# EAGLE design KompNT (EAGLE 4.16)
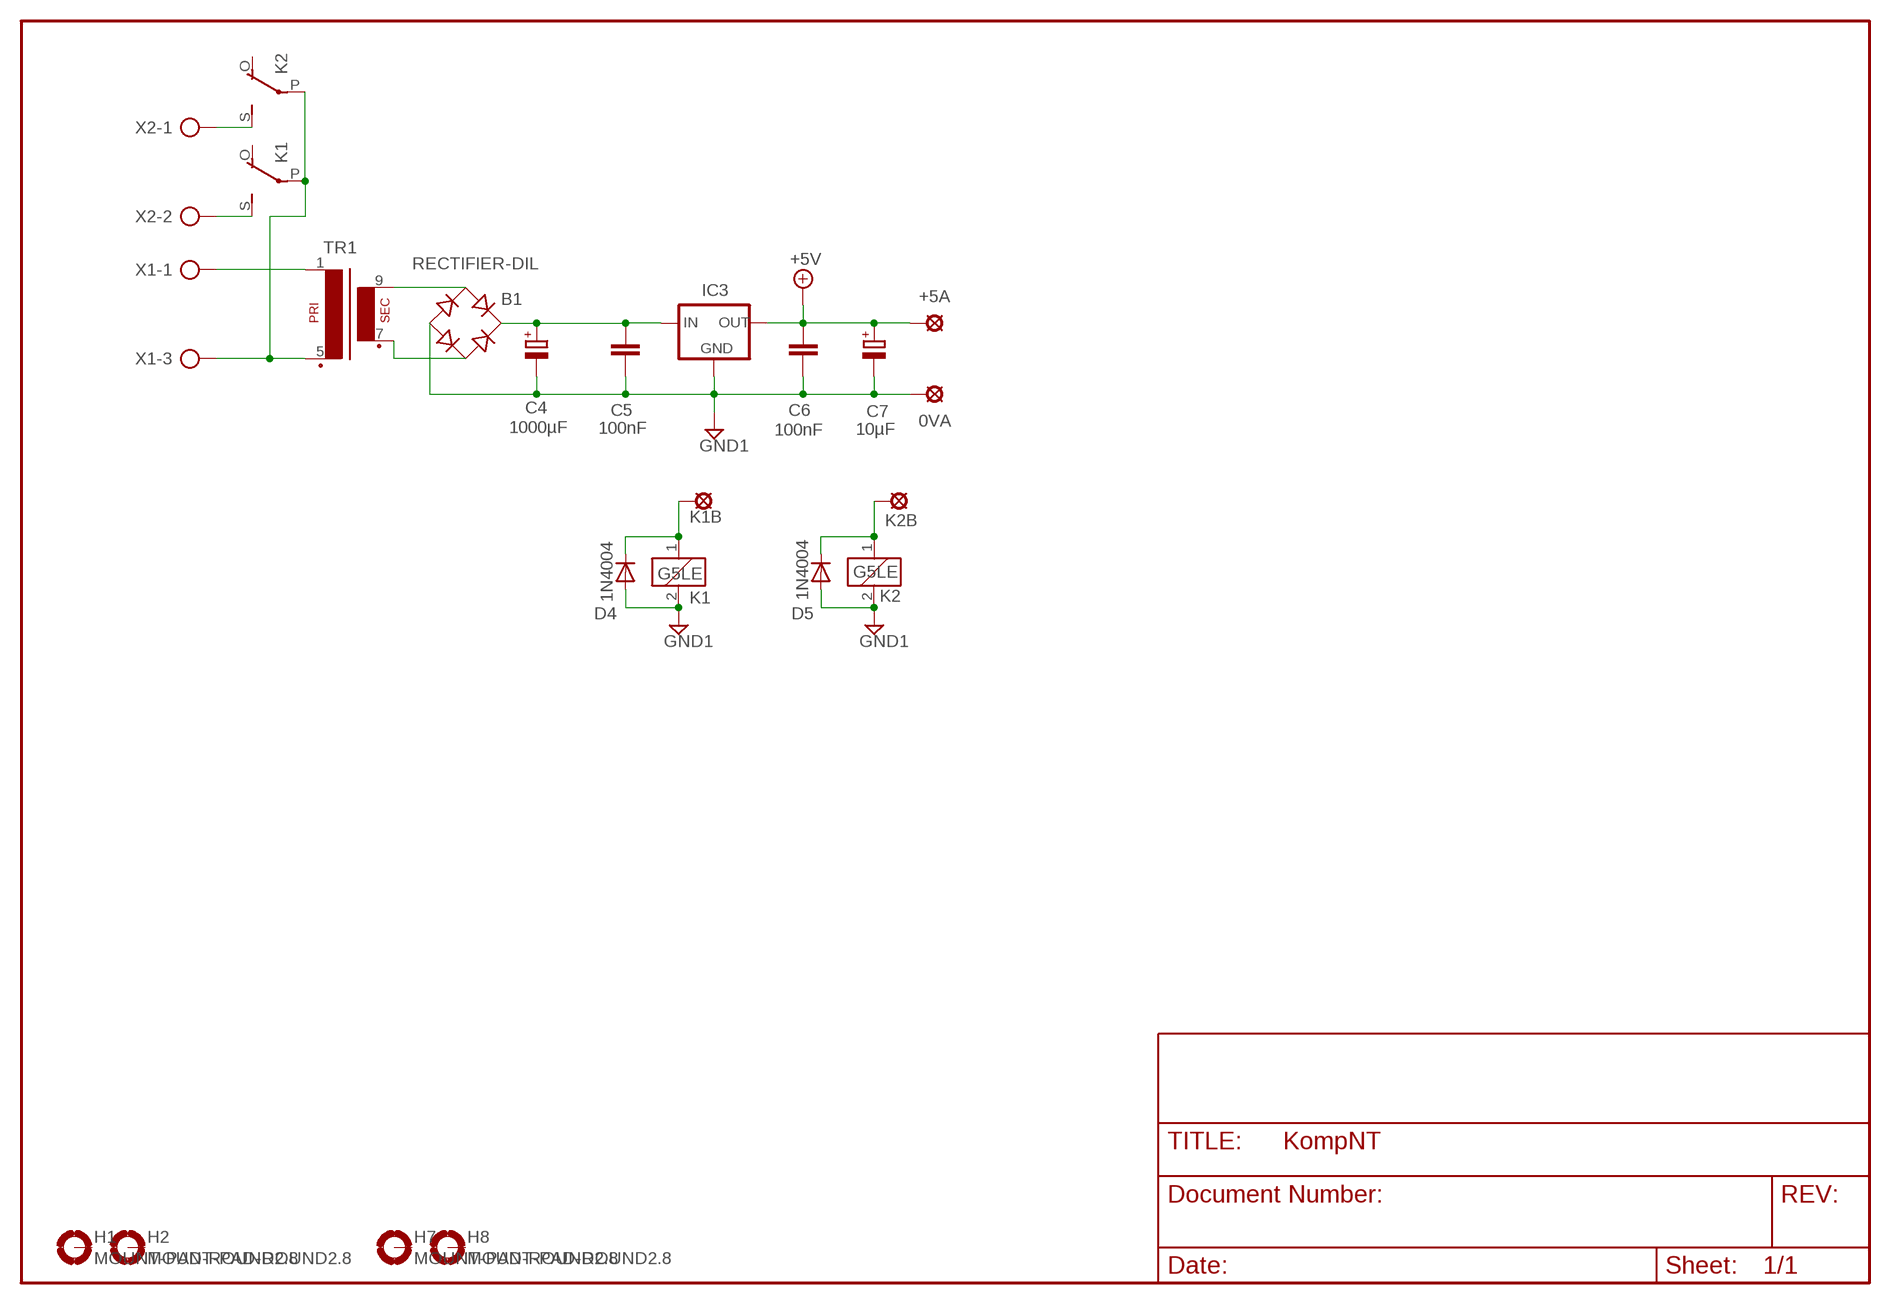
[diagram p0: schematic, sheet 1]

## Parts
0VA  LSP10  [LSP10]
+5A  LSP10  [LSP10]
B1  RECTIFIER-DIL  [B-DIL]
C4  1000µF  CPOL-EUE5-13  [E5-13]
C5  100nF  C-EU025-025X050  [C025-025X050]
C6  100nF  C-EU025-025X050  [C025-025X050]
C7  10µF  CPOL-EUE2.5-5  [E2,5-5]
D4  1N4004  [DO41-10]
D5  1N4004  [DO41-10]
H1  MOUNT-PAD-ROUND2.8  [2,8-PAD]
H2  MOUNT-PAD-ROUND2.8  [2,8-PAD]
H7  MOUNT-PAD-ROUND2.8  [2,8-PAD]
H8  MOUNT-PAD-ROUND2.8  [2,8-PAD]
IC3  78XXS  [78XXS]
K1  G5LE  [G5LE]
K1B  LSP10  [LSP10]
K2  G5LE  [G5LE]
K2B  LSP10  [LSP10]
TR1  EI42-1  [EI42-1]
X1  AK500/3  [AK500/3]
X2  AK500/2  [AK500/2]

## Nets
+5V: +5A.MP C6.2 C7.+ IC3.OUT
GND1: 0VA.MP B1.- C4.- C5.1 C6.1 C7.- D4.A D5.A IC3.GND K1.2 K2.2
N$34: B1.AC1 TR1.9(S4)
N$35: B1.AC2 TR1.7(S3)
N$36: TR1.1 X1.1
N$37: B1.+ C4.+ C5.2 IC3.IN
N$38: D4.C K1.1 K1B.MP
N$39: K1.P(2:P) K2.P(2:P) TR1.5(P2) X1.3
N$40: D5.C K2.1 K2B.MP
N$41: K1.S(2:S) X2.2
N$42: K2.S(2:S) X2.1
Unconnected: H1.B2,8(MOUNT) H2.B2,8(MOUNT) H7.B2,8(MOUNT) H8.B2,8(MOUNT) K1.O(2:O) K2.O(2:O) X1.2

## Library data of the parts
0VA +5A K1B K2B = solpad:LSP10: SOLDER PAD
B1 = rectifier:RECTIFIER-: Rectifier
C4 C7 = rcl:CPOL-EU: POLARIZED CAPACITOR, European symbol
C5 C6 = rcl:C-EU: CAPACITOR, European symbol
D4 D5 = diode:1N4004: DIODE
H1 H2 H7 H8 = holes:MOUNT-PAD-ROUND: MOUNTING PAD, round
IC3 = v-reg:78XXS: VOLTAGE REGULATOR
K1 K2 = relay:G5LE: RELAY 1 x switch, 10 A/120 V AC, 8 A/30 V DC, Omron
TR1 = trafo:EI42-1: TRANSFORMER 1 primary winding, 1 secondary winding ERA
X1 = con-ptr500:AK500/3: CONNECTOR
X2 = con-ptr500:AK500/2: CONNECTOR

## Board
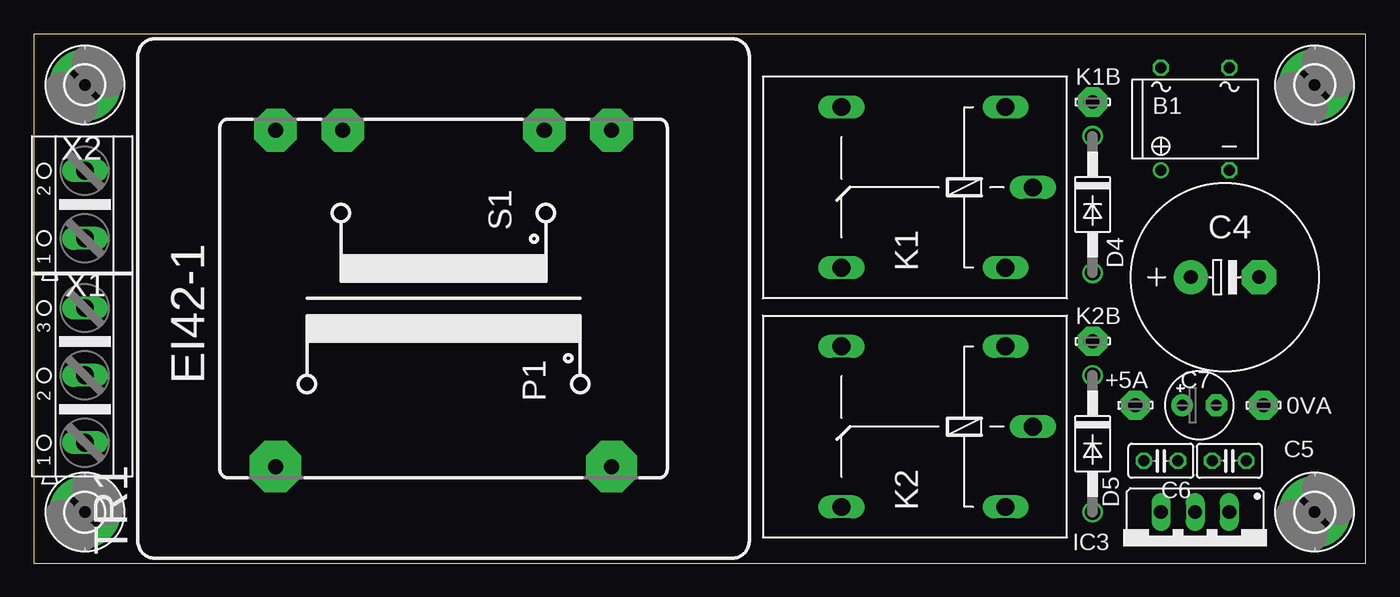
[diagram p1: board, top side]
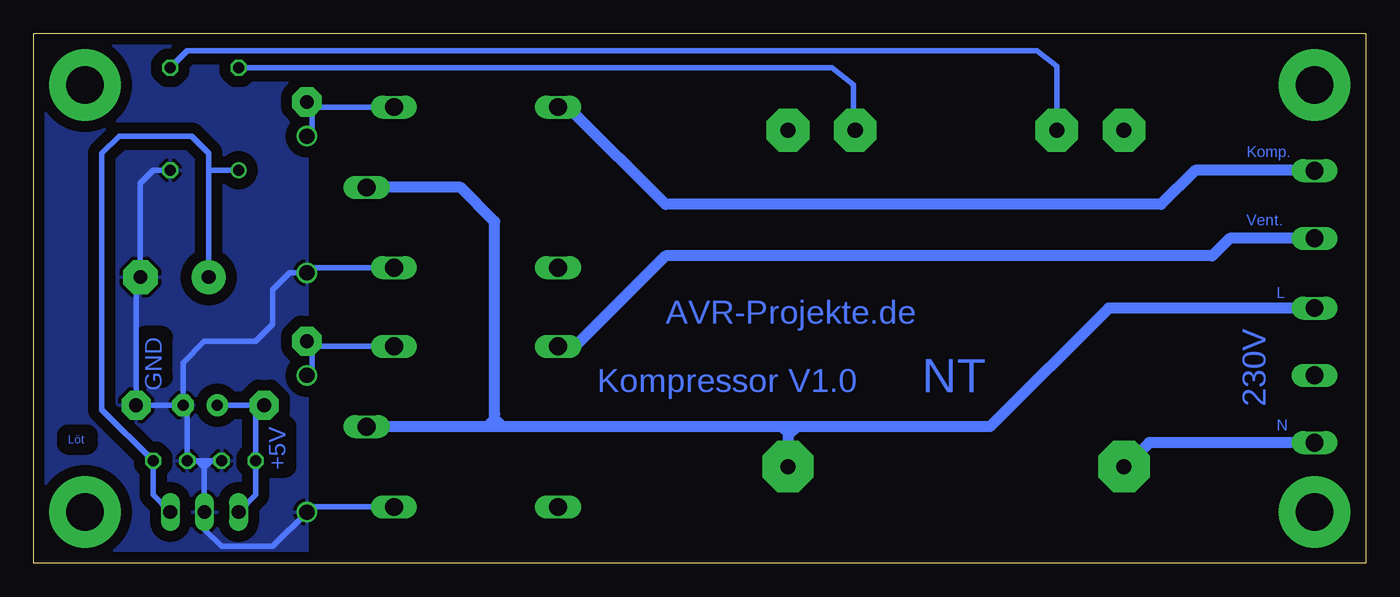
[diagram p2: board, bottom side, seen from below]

Size 99.06 x 39.37 mm. Coordinates in mm from the lower left corner, seen from the top.
Outline: 0,0 99.06,0 99.06,39.37 0,39.37 0,0
Copper layers (1*16): Top 0.035mm / dielectric 1.5mm / Bottom 0.035mm
Design rules "ZWILLING": minimum track width 0.2mm, minimum drill 0.5mm, track to track 0.2mm, track to pad 0.2mm, pad to pad 0.15mm, via to via 0.2mm, smd to smd 0mil, copper to edge 0.2mm, drill to drill 0.2mm, minimum pad ring 0.2mm, minimum via ring 0.2mm, stop-mask expansion 0.1mm, vias tented up to drill 0mil, thermal gap 10mil

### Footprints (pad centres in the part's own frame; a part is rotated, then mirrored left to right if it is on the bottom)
LSP10 = drill 1.016 pad 2.159 octagon: MP 0,0
B-DIL = drill 0.813 round: + -2.54,-3.81 | drill 0.813 octagon: - 2.54,-3.81; AC1 2.54,3.81; AC2 -2.54,3.81
E5-13 = drill 1.016 pad 2.54 round: + -2.54,0 | drill 1.016 pad 2.54 octagon: - 2.54,0
C025-025X050 = drill 0.813 octagon: 1 -1.27,0; 2 1.27,0
E2,5-5 = drill 0.813 pad 1.6 round: + -1.27,0 | drill 0.813 pad 1.6 octagon: - 1.27,0
DO41-10 = drill 1.118 round: A 5.08,0; C -5.08,0
2,8-PAD = drill 2.8 pad 5.334 round: B2,8 0,0
78XXS = drill 1.016 long: GND 0,-2.54; IN -2.54,-2.54; OUT 2.54,-2.54
G5LE = drill 1.321 long: 1 -7.493,-5.969; 2 -7.493,5.969; O 4.699,5.969; P -9.525,0; S 4.699,-5.969
EI42-1 = drill 1.118 pad 3.81 octagon: 1 -12.497,12.497; 5 -12.497,-12.497 | drill 1.118 pad 3.175 octagon: 6 12.497,-12.497; 7 12.497,-7.493; 9 12.497,7.493; 10 12.497,12.497
AK500/3 = drill 1.321 long: 1 -5.004,0; 2 0,0; 3 5.004,0
AK500/2 = drill 1.321 long: 1 -2.515,0; 2 2.515,0

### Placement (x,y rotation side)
0VA  91.44,11.75 0 top
+5A  81.92,11.75 0 top
B1  86.36,33.02 0 top
C4  88.58,21.27 0 top
C5  88.9,7.62 0 top
C6  83.82,7.62 180 top
C7  86.68,11.75 0 top
D4  78.74,26.67 270 top
D5  78.74,8.89 270 top
H1  3.81,3.81 0 top
H2  3.81,35.56 0 top
H7  95.25,35.56 0 top
H8  95.25,3.81 0 top
IC3  86.36,1.27 180 top
K1  64.77,27.94 180 top
K1B  78.74,34.29 0 top
K2  64.77,10.16 180 top
K2B  78.74,16.51 0 top
TR1  30.48,19.68 90 top
X1  3.81,13.97 90 top
X2  3.81,26.67 90 top

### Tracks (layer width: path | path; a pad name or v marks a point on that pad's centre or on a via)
+5V
  Bottom 0.406: IC3.OUT 82.55,5.08 C6.2 82.55,11.75 | 82.55,11.75 +5A.MP | 82.55,11.75 C7.+
GND1
  Bottom 0.254: 85.72,7.62 86.36,6.99 87,7.62 | 86.68,7.62 86.36,7.3 86.04,7.62
  Bottom 0.406: K1.2 78.36,21.97 D4.A 80.01,21.59 81.28,20.32 81.28,17.78 82.55,16.51 86.36,16.51 87.95,14.92 C7.- | K2.2 78.36,4.19 D5.A 81.28,1.27 85.09,1.27 86.36,2.54 IC3.GND 86.36,6.99 86.36,7.3 86.36,7.62 | 86.36,7.62 86.04,7.62 85.72,7.62 C6.1 | 86.36,7.62 86.68,7.62 87,7.62 C5.1 | B1.- 90.17,29.21 91.12,28.26 C4.- 91.44,20.95 0VA.MP C7.- | C5.1 87.63,7.3 | C7.- 87.63,11.43 C5.1
  pour Bottom (isolate 0.813, rank 2): 78.74,39.37 78.74,-1.27 100.33,-1.27 100.33,39.37
N$34
  Bottom 0.406: TR1.9 22.99,36.96 24.45,38.1 87.63,38.1 B1.AC1
N$35
  Bottom 0.406: TR1.7 37.97,31.62 38.1,31.75 38.1,35.56 39.69,36.83 B1.AC2
N$36
  Bottom 0.406: 17.78,7.3 TR1.1
  Bottom 0.813: X1.1 16.12,8.97 17.78,7.3
N$37
  Bottom 0.406: IC3.IN 90.17,5.08 C5.2 93.98,11.43 93.98,30.48 92.71,31.75 87.31,31.75 86.04,30.48 86.04,29.21 | 86.04,29.21 C4.+ | 86.04,29.21 B1.+
N$38
  Bottom 0.406: K1.1 78.36,33.91 | 78.36,33.91 K1B.MP | 78.36,33.91 78.36,32.13 D4.C
N$39
  Bottom 0.254: 41.91,10.16 42.86,9.21 43.81,10.16 | 64.14,10.48 64.77,11.11 65.41,10.48
  Bottom 0.406: TR1.5 42.86,7.62 | 43.18,10.16 42.98,9.96
  Bottom 0.813: X1.3 19.13,18.97 27.94,10.16 41.91,10.16 43.18,10.16 43.81,10.16 64.77,10.16 | 64.77,10.16 K2.P | 42.98,9.96 TR1.5 | K1.P 67.31,27.94 64.77,25.4 64.77,11.11 64.77,10.16
N$40
  Bottom 0.406: K2.1 78.36,16.13 | 78.36,16.13 K2B.MP | 78.36,16.13 78.36,14.35 D5.C
N$41
  Bottom 0.406: X2.2 3.81,29.21
  Bottom 0.813: 3.81,29.21 12.7,29.21 15.24,26.67 52.07,26.67 59.05,33.66 60.01,33.66 60.01,33.85 K1.S
N$42
  Bottom 0.813: X2.1 10.13,24.16 11.43,22.86 52.07,22.86 59.05,15.88 60.33,15.88 K2.S

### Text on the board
Bottom: Komp. | Vent. | L | AVR-Projekte.de | 230V | GND | NT | Kompressor V1.0 | N | +5V | Löt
